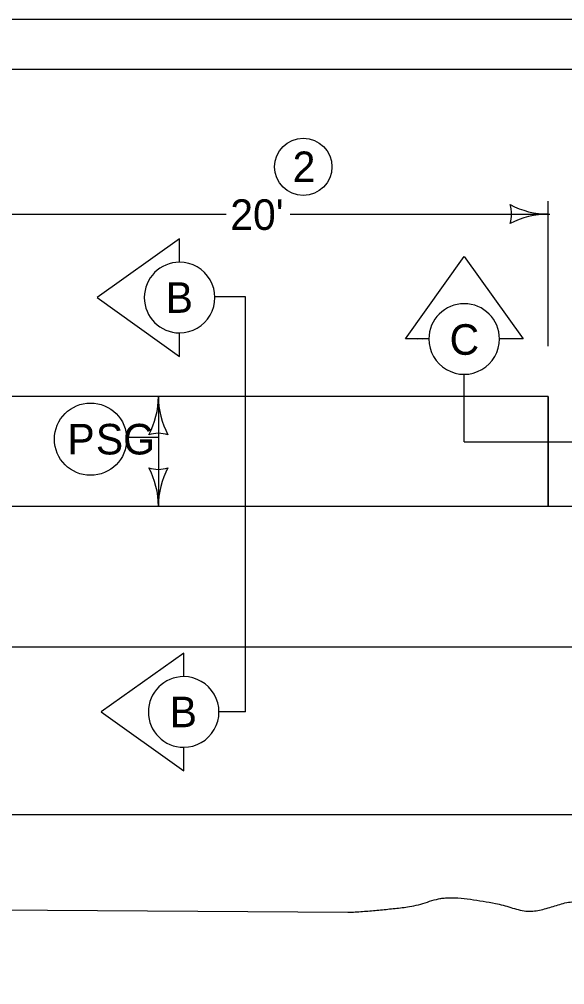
# Model space of a CAD drawing. Extents: x 6410 to 81668, y 3928 to 11667.
# Drawn here: x 11530 to 11815, y 9439 to 9944 of the extents above; entities that cross this region are included whole.
import ezdxf

# ---------------------------------------------------------------- set-up
doc = ezdxf.new("R2010")
doc.units = 0
for name, color, linetype in [('dsnNonPlotable', 7, 'Continuous'), ('dsnShtPlotShapeBatchPrint', 7, 'Continuous'), ('dsnStdBlockModified', 7, 'Continuous'), ('Level 10', 7, 'Continuous'), ('Level 11', 7, 'Continuous'), ('Level 7', 7, 'Continuous'), ('Level 8', 7, 'Continuous')]:
    doc.layers.add(name, color=color, linetype=linetype)

msp = doc.modelspace()

# ---------------------------------------------------------------- linework, layer by layer
at = {"layer": 'dsnNonPlotable'}
msp.add_line((10153.18, 9917.9), (13248.87, 9917.9), dxfattribs=at)
at = {"layer": 'dsnShtPlotShapeBatchPrint'}
for p, q in [((11806.49, 9772.84), (11806.49, 9848.85)), ((11501.75, 9842.03), (11637.75, 9842.03)), ((11671.27, 9842.03), (11807.27, 9842.03)), ((11806.49, 9746.48), (11501.75, 9746.48)), ((11602.33, 9746.48), (11602.33, 9689.17)), ((11806.49, 9689.17), (11806.49, 9746.48)), ((11585.76, 9725.3), (11602.33, 9725.3)), ((10774.8, 9689.17), (11806.49, 9689.17))]:
    msp.add_line(p, q, dxfattribs=at)
msp.add_circle((11566.83, 9724.18), 18.93, dxfattribs=at)
msp.add_circle((11566.83, 9724.18), 18.93, dxfattribs=at)
for centre, radius, start, end in [((11770.86, 9842.03), 16.42, 342.2666, 17.7333), ((11806.49, 9884.53), 42.5, 241.9275, 270), ((11806.49, 9799.53), 42.5, 90, 118.0725), ((11559.83, 9746.48), 42.5, 331.9275, 0), ((11644.83, 9746.48), 42.5, 180, 208.0725), ((11602.33, 9710.84), 16.42, 72.2666, 107.7334), ((11602.33, 9724.8), 16.42, 252.2666, 287.7333), ((11559.83, 9689.17), 42.5, 360, 28.0725), ((11644.83, 9689.17), 42.5, 151.9275, 180)]:
    msp.add_arc(centre, radius, start, end, dxfattribs=at)
at = {"layer": 'dsnStdBlockModified'}
for p, q in [((11740.87, 9776.56), (11731.63, 9776.64)), ((11738.24, 9776.58), (11731.63, 9776.64)), ((11806.49, 9746.48), (11501.75, 9746.48)), ((11806.49, 9746.48), (11806.49, 9689.17)), ((10369.64, 9689.17), (11983.35, 9689.17)), ((10369.86, 9615.54), (11983.65, 9615.54)), ((11372.34, 9478.91), (11701.54, 9476.45))]:
    msp.add_line(p, q, dxfattribs=at)
msp.add_spline([(11701.54, 9476.45), (11703.54, 9476.56), (11711.11, 9477.04), (11718.68, 9477.71), (11726.23, 9478.51), (11733.76, 9479.41), (11738.51, 9480.41), (11743.19, 9481.85), (11747.86, 9483.22), (11750.21, 9483.71), (11752.58, 9483.98), (11759.12, 9483.96), (11765.71, 9483.3), (11772.29, 9482.27), (11778.81, 9481.13), (11782.82, 9480.19), (11786.79, 9478.98), (11790.77, 9477.85), (11794.78, 9477.13), (11798.32, 9477.1), (11801.87, 9477.61), (11808.98, 9479.53), (11816.12, 9481.54), (11823.29, 9482.27), (11837.82, 9481.29), (11852.37, 9479.98), (11859.09, 9479.16), (11865.79, 9478.18), (11872.49, 9477.23), (11879.17, 9476.56), (11884.92, 9477.13), (11890.6, 9478.95), (11896.26, 9481.01), (11901.98, 9482.27), (11909.48, 9482.77), (11917.08, 9482.9), (11928.47, 9482.21), (11932.2, 9481.7), (11939.22, 9479.88), (11946.12, 9477.31), (11953.04, 9474.94), (11960.14, 9473.71), (11981.25, 9472.7)], degree=3, dxfattribs=at)
at = {"layer": 'Level 10'}
for p, q in [((11648.01, 9798.63), (11632.23, 9798.63)), ((11648.01, 9581.35), (11648.01, 9798.63)), ((11762.44, 9722.72), (11762.44, 9758.16)), ((11762.44, 9722.72), (11850.54, 9722.72)), ((11648.01, 9581.35), (11634.05, 9581.35))]:
    msp.add_line(p, q, dxfattribs=at)
for points in [[(11613.44, 9816.82), (11613.44, 9829.14), (11570.31, 9798.33), (11613.44, 9767.52), (11613.44, 9779.84)], [(11743.96, 9776.64), (11731.63, 9776.64), (11762.44, 9819.78), (11793.25, 9776.64), (11780.93, 9776.64)], [(11615.57, 9599.83), (11615.57, 9612.16), (11572.43, 9581.35), (11615.57, 9550.54), (11615.57, 9562.86)]]:
    msp.add_lwpolyline(points, dxfattribs=at)
for centre, start, end in [((11613.44, 9798.33), 90.0008, 269.9992), ((11613.44, 9798.33), 269.9992, 90.0008), ((11762.44, 9776.64), 0.0008, 179.9992), ((11762.44, 9776.64), 179.9992, 0.0008), ((11615.57, 9581.35), 90.0008, 269.9992), ((11615.57, 9581.35), 269.9992, 90.0008)]:
    msp.add_arc(centre, 18.49, start, end, dxfattribs=at)
at = {"layer": 'Level 11'}
msp.add_line((10353.26, 9527.62), (11995.29, 9527.62), dxfattribs=at)
at = {"layer": 'Level 7'}
msp.add_circle((11678.2, 9866.78), 15, dxfattribs=at)
at = {"layer": 'Level 8'}
msp.add_lwpolyline([(10132.52, 9944.02), (13267.53, 9944.02), (13267.53, 7924.02), (10132.52, 7924.02)], close=True, dxfattribs=at)

# ---------------------------------------------------------------- texts
at = {"layer": 'dsnShtPlotShapeBatchPrint'}
for s, p in [("20'", (11639.99, 9833.75)), ('P', (11554.7, 9716.18)), ('SG', (11569.61, 9716.18))]:
    msp.add_text(s, height=16, dxfattribs=at).set_placement(p)
at = {"layer": 'Level 10'}
for s, p in [('B', (11606.17, 9790.33)), ('C', (11754.81, 9768.37)), ('B', (11608.26, 9573.35))]:
    msp.add_text(s, height=16, dxfattribs=at).set_placement(p)
at = {"layer": 'Level 7'}
msp.add_text('2', height=16, dxfattribs=at).set_placement((11672.62, 9858.78))

doc.saveas('drawing.dxf')
